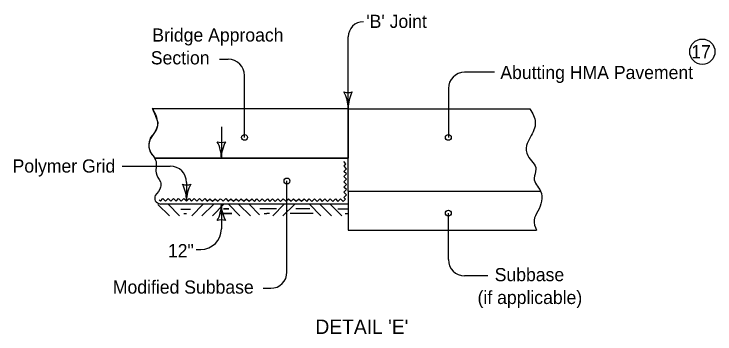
# Model space of a CAD drawing. Extents: x 10028 to 81668, y 6395 to 11634.
# Drawn here: x 23128 to 23980, y 6709 to 7097 of the extents above; entities that cross this region are included whole.
import ezdxf

# ---------------------------------------------------------------- set-up
doc = ezdxf.new("R2010")
doc.units = 0
for name, color, linetype in [('dsnCellElements', 7, 'Continuous'), ('dsnStgShadingPropPav', 7, 'Continuous'), ('ShtPlotIdentification', 7, 'Continuous')]:
    doc.layers.add(name, color=color, linetype=linetype)

msp = doc.modelspace()

# ---------------------------------------------------------------- linework, layer by layer
at = {"layer": 'dsnStgShadingPropPav'}
for centre in [(23408.58, 6947.43), (23656.27, 6947.43), (23460.12, 6894.5), (23656.27, 6855.41)]:
    msp.add_circle(centre, 3.54, dxfattribs=at)
at = {"layer": 'ShtPlotIdentification'}
for p, q in [((23534.47, 6982.62), (23534.47, 7069.41)), ((23378.15, 7042.37), (23388.78, 7042.37)), ((23408.58, 6947.43), (23408.58, 7022.57)), ((23712.55, 7026.51), (23676.07, 7026.51)), ((23656.27, 7006.71), (23656.27, 6947.43)), ((23534.53, 6982.08), (23296.45, 6982.08)), ((23534.53, 6982.08), (23296.77, 6982.08)), ((23534.53, 6922.09), (23534.53, 6982.08)), ((23534.53, 6982.08), (23755.44, 6982.08)), ((23534.53, 6982.08), (23534.53, 6922.09)), ((23380.4, 6960.47), (23380.4, 6922.09)), ((23534.53, 6922.09), (23299.54, 6922.09)), ((23299.55, 6922.09), (23534.53, 6922.09)), ((23534.53, 6882.09), (23534.53, 6922.09)), ((23259.78, 6912.54), (23318.33, 6912.54)), ((23338.13, 6892.74), (23338.13, 6870.47)), ((23460.12, 6783.95), (23460.12, 6894.5)), ((23534.05, 6893.61), (23534.05, 6893.61)), ((23534.53, 6882.09), (23768.32, 6882.09)), ((23534.53, 6882.09), (23534.53, 6834.85)), ((23303.22, 6866), (23317.22, 6852)), ((23534.05, 6866.22), (23306.51, 6866.22)), ((23336.94, 6866.22), (23308.63, 6866.22)), ((23315.55, 6866.22), (23329.54, 6852.22)), ((23343.02, 6860.02), (23331.11, 6860.02)), ((23336.94, 6866.22), (23336.94, 6866.22)), ((23435.5, 6866.22), (23336.94, 6866.22)), ((23336.94, 6866.22), (23336.94, 6866.22)), ((23358.34, 6866.22), (23344.34, 6852.22)), ((23370.66, 6866), (23356.66, 6852)), ((23383.54, 6866.22), (23369.54, 6852.22)), ((23380.4, 6866.46), (23380.4, 6836.33)), ((23382.99, 6860.78), (23389.45, 6860.78)), ((23382.99, 6860.78), (23389.45, 6860.78)), ((23389.45, 6860.78), (23382.99, 6860.78)), ((23389.45, 6860.78), (23382.99, 6860.78)), ((23388.9, 6866.22), (23402.9, 6852.22)), ((23401.77, 6866), (23415.78, 6852)), ((23414.1, 6866.22), (23426.94, 6853.38)), ((23447.41, 6860.8), (23427.2, 6860.8)), ((23435.5, 6866.22), (23435.5, 6866.22)), ((23534.05, 6866.22), (23435.5, 6866.22)), ((23435.5, 6866.22), (23435.5, 6866.22)), ((23456.9, 6866.22), (23442.89, 6852.22)), ((23444.47, 6860.8), (23444.47, 6860.8)), ((23469.22, 6866), (23455.22, 6852)), ((23488.01, 6860.78), (23470.86, 6860.78)), ((23488.01, 6860.78), (23483.1, 6860.78)), ((23487.45, 6866.22), (23501.45, 6852.22)), ((23500.33, 6866), (23514.33, 6852)), ((23512.66, 6866.22), (23526.66, 6852.22)), ((23522.14, 6860.8), (23534.05, 6860.8)), ((23525.08, 6860.8), (23525.08, 6860.8)), ((23334.62, 6855.06), (23337.85, 6855.06)), ((23379.19, 6854.98), (23393.24, 6854.98)), ((23379.19, 6854.98), (23393.24, 6854.98)), ((23393.24, 6854.98), (23379.19, 6854.98)), ((23393.24, 6854.98), (23379.19, 6854.98)), ((23432.26, 6855.06), (23435.5, 6855.06)), ((23438.73, 6855.06), (23435.5, 6855.06)), ((23438.73, 6855.06), (23438.73, 6855.06)), ((23491.8, 6854.98), (23464, 6854.98)), ((23530.82, 6855.06), (23530.82, 6855.06)), ((23530.82, 6855.06), (23534.05, 6855.06)), ((23656.27, 6798.99), (23656.27, 6855.41)), ((23534.53, 6834.85), (23763.34, 6834.85)), ((23349.75, 6811.33), (23355.4, 6811.33)), ((23704.14, 6779.19), (23676.07, 6779.19)), ((23431.22, 6764.15), (23440.31, 6764.15))]:
    msp.add_line(p, q, dxfattribs=at)
for points in [[(23531.76, 6915.49), (23529.16, 6918.1)], [(23531.26, 6872.62), (23529.36, 6874.53), (23532.54, 6877.68), (23529.38, 6880.86), (23532.56, 6884.02), (23529.4, 6887.2), (23532.57, 6890.35), (23529.41, 6893.53), (23532.59, 6896.69), (23529.43, 6899.87), (23532.6, 6903.02), (23529.44, 6906.21), (23532.63, 6909.37), (23529.46, 6912.54), (23531.74, 6915.47)], [(23304.67, 6871.6), (23306.26, 6870.02), (23309.43, 6873.18), (23312.59, 6870), (23315.77, 6873.16), (23318.93, 6869.98), (23322.11, 6873.14), (23325.27, 6869.96), (23328.44, 6873.12), (23331.6, 6869.95), (23334.78, 6873.11), (23337.94, 6869.93), (23341.11, 6873.09), (23344.27, 6869.92), (23347.45, 6873.08), (23350.61, 6869.9), (23353.79, 6873.06), (23356.95, 6869.88), (23360.12, 6873.04), (23363.28, 6869.87), (23366.46, 6873.02), (23369.61, 6869.85), (23372.79, 6873.01), (23375.95, 6869.83), (23379.13, 6872.99), (23380.55, 6871.86)], [(23380.9, 6871.48), (23382.47, 6869.88), (23385.66, 6873.05), (23388.81, 6869.87), (23391.99, 6873.03), (23395.15, 6869.85), (23398.32, 6873.01), (23401.48, 6869.83), (23404.66, 6872.99), (23407.82, 6869.81), (23411, 6872.98), (23414.16, 6869.8), (23417.34, 6872.96), (23420.49, 6869.78), (23423.67, 6872.94), (23426.83, 6869.77), (23430, 6872.93), (23433.16, 6869.75), (23436.34, 6872.91), (23439.5, 6869.73), (23442.68, 6872.89), (23445.83, 6869.72), (23449.01, 6872.88), (23452.17, 6869.69), (23455.34, 6872.86), (23456.77, 6871.73)], [(23457.15, 6871.45), (23458.73, 6869.85), (23461.91, 6873.01), (23465.07, 6869.84), (23468.25, 6873), (23471.41, 6869.82), (23474.58, 6872.98), (23477.74, 6869.8), (23480.92, 6872.97), (23484.08, 6869.79), (23487.25, 6872.95), (23490.41, 6869.77), (23493.59, 6872.93), (23496.75, 6869.75), (23499.93, 6872.91), (23503.09, 6869.73), (23506.26, 6872.89), (23509.42, 6869.72), (23512.6, 6872.88), (23515.76, 6869.7), (23518.93, 6872.86), (23522.09, 6869.69), (23525.27, 6872.85), (23528.43, 6869.67), (23531.33, 6872.56)]]:
    msp.add_lwpolyline(points, dxfattribs=at)
msp.add_circle((23965, 7051.55), 15.36, dxfattribs=at)
for centre, radius, start, end in [((23553.04, 7069.42), 18.56, 90, 180), ((23388.79, 7022.56), 19.8, 0, 90), ((23676.08, 7006.71), 19.8, 90, 180), ((23534.47, 7018.46), 16.51, 252.26665, 287.73335), ((23491.72, 6982.62), 42.75, 360, 28.07249), ((23534.47, 7018.46), 16.51, 252.26665, 287.73335), ((23491.72, 6982.62), 42.75, 360, 28.07249), ((23577.22, 6982.62), 42.75, 151.92751, 180), ((23577.22, 6982.62), 42.75, 151.92751, 180), ((23380.4, 6957.93), 16.51, 252.26665, 287.73335), ((23337.65, 6922.09), 42.75, 360, 28.07249), ((23423.15, 6922.09), 42.75, 151.92751, 180), ((23318.33, 6892.74), 19.8, 0, 90), ((23338.13, 6906.32), 16.51, 252.26665, 287.73335), ((23295.38, 6870.47), 42.75, 0, 28.07249), ((23380.88, 6870.47), 42.75, 151.92751, 180), ((23337.65, 6866.46), 42.75, 331.92751, 360), ((23423.15, 6866.46), 42.75, 180, 208.07249), ((23380.4, 6830.62), 16.51, 72.26665, 107.73335), ((23355.4, 6836.33), 25, 270, 0), ((23676.08, 6798.98), 19.8, 180, 270), ((23440.32, 6783.95), 19.8, 270, 360)]:
    msp.add_arc(centre, radius, start, end, dxfattribs=at)
for points in [[(23296.45, 6982.88), (23302.54, 6967.62), (23302.4, 6960.6), (23292.62, 6941.39), (23294.04, 6930.05), (23300.52, 6919.98), (23301.13, 6904.53), (23306.51, 6893.61)], [(23755.44, 6982.08), (23761.97, 6965.7), (23755.89, 6947.45), (23751.33, 6937.57), (23752.85, 6925.4), (23762.73, 6908.67), (23760.45, 6898.03), (23768.32, 6882.09), (23765.02, 6857.72), (23760.45, 6847.08), (23763.34, 6834.79)], [(23306.51, 6893.61), (23306.51, 6887.15), (23299.98, 6876.94)], [(23299.98, 6876.94), (23299.98, 6870.5), (23306.51, 6866.22)]]:
    msp.add_spline(points, degree=3, dxfattribs=at)
msp.add_open_spline([(23296.77, 6982.08), (23298.7, 6977.26), (23300.62, 6972.44), (23302.54, 6967.62), (23303.41, 6965.45), (23302.86, 6962.84), (23302.4, 6960.6), (23301, 6953.74), (23293.76, 6948.1), (23292.62, 6941.39), (23292.01, 6937.84), (23292.71, 6933.61), (23294.04, 6930.05), (23295.15, 6927.07), (23297.91, 6924.79), (23299.55, 6922.09)], degree=3, dxfattribs=at)

# ---------------------------------------------------------------- texts
at = {"layer": 'dsnCellElements'}
for s, p in [("'B' Joint", (23556.55, 7080.44)), ('Bridge Approach', (23296.52, 7063.84)), ('17', (23951.47, 7043.55)), ('Section', (23294.66, 7036.12)), ('Abutting HMA Pavement', (23719.47, 7018.33)), ('Polymer Grid', (23126.62, 6904.72)), ('12"', (23315.43, 6801.85)), ('Subbase', (23712.6, 6772.79)), ('Modified Subbase', (23248.47, 6757.65)), ('(if applicable)', (23691.76, 6745.07))]:
    msp.add_text(s, height=16, dxfattribs=at).set_placement(p)
at = {"layer": 'ShtPlotIdentification'}
msp.add_text("DETAIL 'E'", height=17.5, dxfattribs=at).set_placement((23494.67, 6708.69))

doc.saveas('drawing.dxf')
